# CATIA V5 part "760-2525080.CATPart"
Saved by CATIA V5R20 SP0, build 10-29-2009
Part number: 760-2525080
Source: Unknown
Property "A": "25.000"
Property "ARTICLENO": "760-2525080"
Property "BOMINFO": "760-2525080"
Property "CODE": "760-2525080"
Property "K": "40.000"
Property "L": "80.000"
Property "LINA": "760-2525080"
Property "NB": "760-2525080"
Property "NBSYN": "$CODE."
Property "NN": "760"
Property "NT": "Key"
Property "SUPPLIER": "CF"
Bounding box of the stored display mesh (mm): x -40 to 40, y 0 to 25, z -12.5 to 12.5
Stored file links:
  C:\Users\Utente\Desktop\3D files 760\760-2525080.CATPart
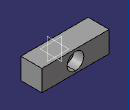
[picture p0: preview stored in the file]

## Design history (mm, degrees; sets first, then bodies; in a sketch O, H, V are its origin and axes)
Body1 "Geometry.1" (main body)
  Solid1 "760-2525080.catpart": solid without history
